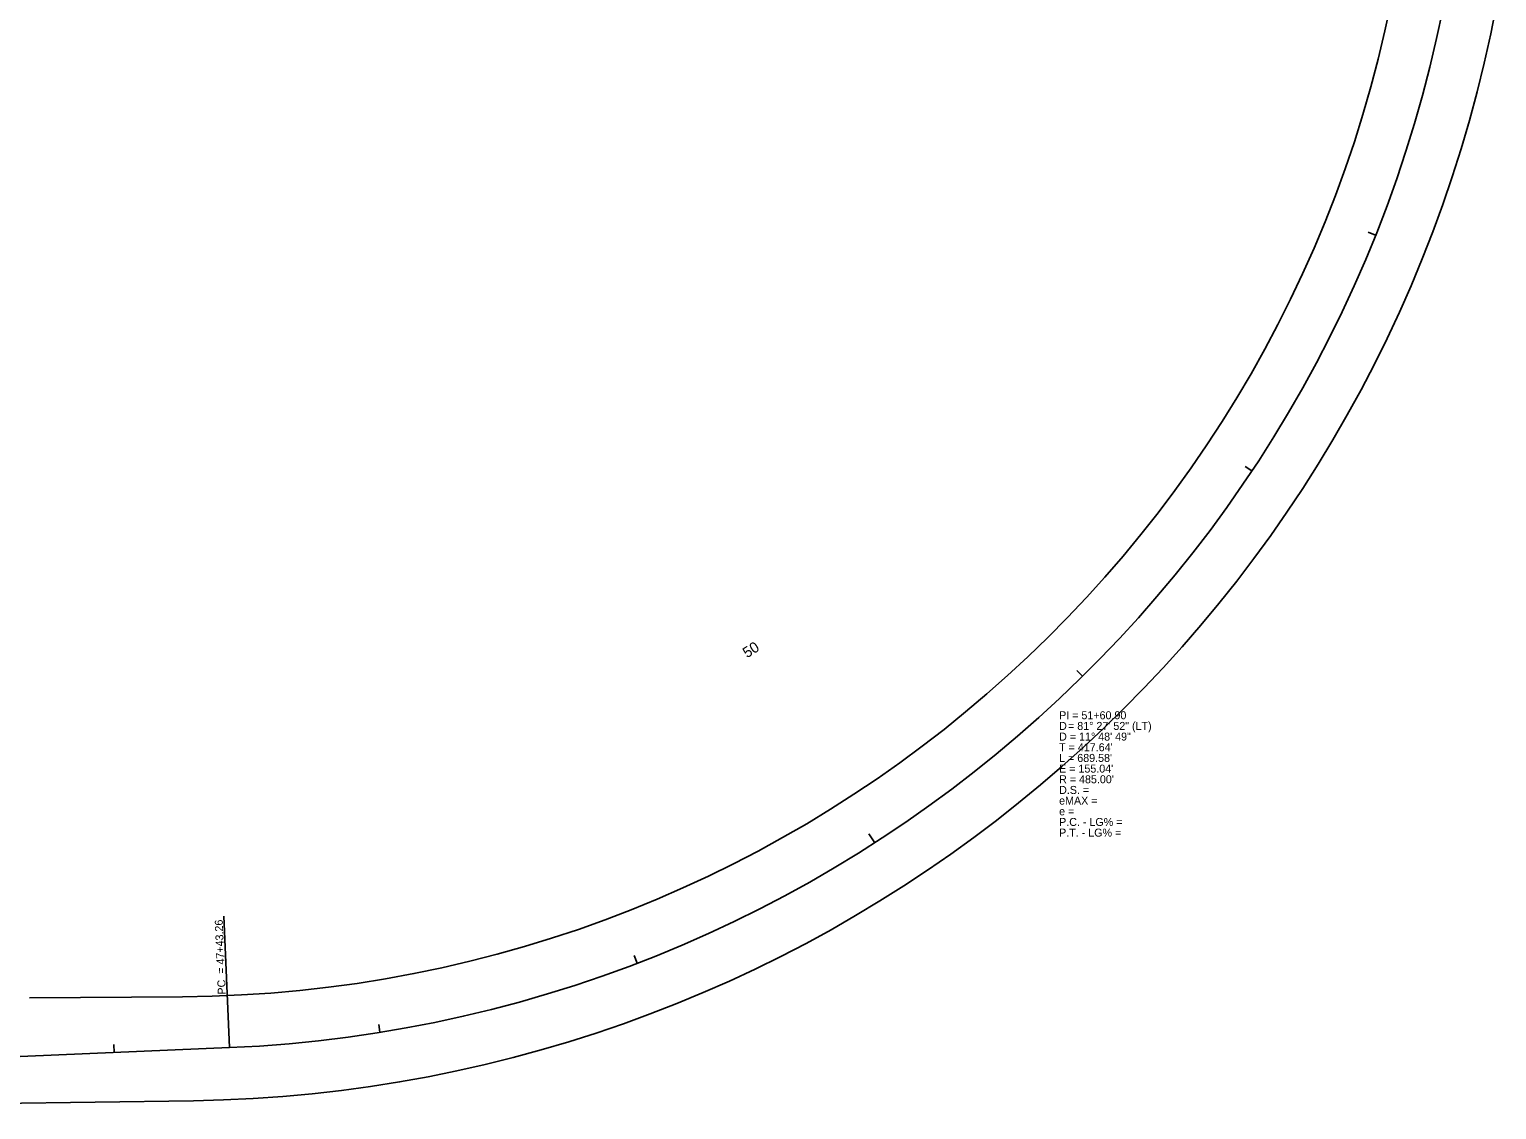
# Model space of a CAD drawing. Extents: x 2004390 to 2007638, y 1136392 to 1138193.
# Drawn here: x 2006993 to 2007543, y 1137265 to 1137670 of the extents above; entities that cross this region are included whole.
import ezdxf

# ---------------------------------------------------------------- set-up
doc = ezdxf.new("R2010")
doc.units = 0
for name, color, linetype in [('RD_HC_Cl', 7, 'Continuous'), ('RD_HC_Data', 7, 'Continuous'), ('RD_HC_Data_Tic', 7, 'Continuous'), ('RD_HC_TX_Sta20', 7, 'Continuous'), ('RD_PD_Final_TrvlWay', 7, 'Continuous')]:
    doc.layers.add(name, color=color, linetype=linetype)

msp = doc.modelspace()

# ---------------------------------------------------------------- linework, layer by layer
at = {"layer": 'RD_HC_Cl'}
msp.add_line((2006775.18, 1137275.34), (2007068.03, 1137287.9), dxfattribs=at)
msp.add_arc((2007047.25, 1137772.45), 485, 272.4547, 353.919, dxfattribs=at)
at = {"layer": 'RD_HC_Data'}
msp.add_line((2007068.03, 1137287.9), (2007065.91, 1137337.12), dxfattribs=at)
at = {"layer": 'RD_HC_Data_Tic'}
for p, q in [((2007497.65, 1137592.54), (2007494.86, 1137593.65)), ((2007451.28, 1137504.14), (2007448.78, 1137505.8)), ((2007387.79, 1137427.11), (2007385.68, 1137429.25)), ((2007309.87, 1137364.71), (2007307.71, 1137368.07)), ((2007220.84, 1137319.58), (2007219.76, 1137322.38)), ((2007124.44, 1137293.63), (2007123.97, 1137296.59)), ((2007024.81, 1137286.04), (2007024.68, 1137289.04))]:
    msp.add_line(p, q, dxfattribs=at)
at = {"layer": 'RD_PD_Final_TrvlWay'}
for p, q in [((2006993, 1137306.57), (2007050.44, 1137306.96)), ((2006820.7, 1137264.64), (2007054.51, 1137268))]:
    msp.add_line(p, q, dxfattribs=at)
for radius, start, end in [(465.5, 270.3929, 353.919), (504.5, 270.8238, 349.3164)]:
    msp.add_arc((2007047.25, 1137772.45), radius, start, end, dxfattribs=at)

# ---------------------------------------------------------------- texts
at = {"layer": 'RD_HC_Data'}
for s, p in [('PI = 51+60.90', (2007379, 1137411)), ('D', (2007379, 1137407)), ('   = 81%%d 27\' 52" (LT)', (2007379, 1137407)), ('D = 11%%d 48\' 49"', (2007379, 1137403)), ("T = 417.64'", (2007379, 1137399)), ("L = 689.58'", (2007379, 1137395)), ("E = 155.04'", (2007379, 1137391)), ("R = 485.00'", (2007379, 1137387)), ('D.S. = ', (2007379, 1137383)), ('eMAX = ', (2007379, 1137379)), ('e = ', (2007379, 1137375)), ('P.C. - LG% = ', (2007379, 1137371)), ('P.T. - LG% = ', (2007379, 1137367))]:
    msp.add_text(s, height=3, dxfattribs=at).set_placement(p)
msp.add_text('PC  = 47+43.26', height=3, rotation=92.4547, dxfattribs=at).set_placement((2007066.67, 1137307.86))
at = {"layer": 'RD_HC_TX_Sta20'}
msp.add_text('50', height=4, rotation=32.785, dxfattribs=at).set_placement((2007262.03, 1137433.81))

doc.saveas('drawing.dxf')
